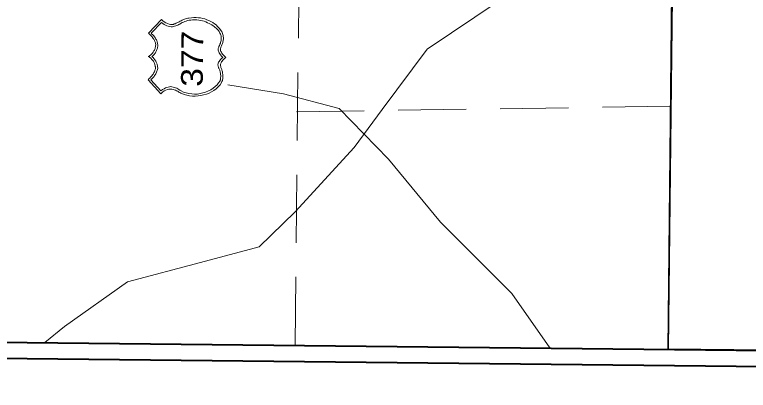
# Model space of a CAD drawing. Extents: x 2356576 to 2377878, y 6966390 to 6990634.
# Drawn here: x 2366013.1 to 2366242.4, y 6968641.2 to 6968758.5 of the extents above; entities that cross this region are included whole.
import ezdxf

# ---------------------------------------------------------------- set-up
doc = ezdxf.new("R2010")
doc.units = 0
doc.header["$LTSCALE"] = 7.1
doc.linetypes.add('MEDIUM_DASHED', pattern=[4.5, 3, -1.5])
doc.layers.add('19', color=7, linetype='Continuous', lineweight=13)
doc.layers.add('8', color=7, linetype='Continuous', lineweight=13)

msp = doc.modelspace()

# ---------------------------------------------------------------- linework, layer by layer
at = {"layer": '19', "lineweight": 35}
for q in [(2366226.339, 6969461.286), (2366922.891, 6968646.236)]:
    msp.add_line((2366217.375, 6968654.072), q, dxfattribs=at)
at = {"layer": '19', "linetype": 'MEDIUM_DASHED'}
for p, q in [((2366100.797, 6968655.28), (2366107.007, 6969254.676)), ((2366218.161, 6968729.912), (2366101.192, 6968728.184))]:
    msp.add_line(p, q, dxfattribs=at)
at = {"layer": '19', "lineweight": 40}
msp.add_lwpolyline([(2363758.773, 6990629.355), (2367158.576, 6990592.767), (2366922.891, 6968646.236), (2363523.088, 6968682.826)], close=True, dxfattribs=at)
at = {"layer": '19', "lineweight": 25}
msp.add_lwpolyline([(2365597.072, 6968660.498), (2366217.375, 6968654.072), (2366223.585, 6969253.468), (2365603.282, 6969259.894)], dxfattribs=at)
at = {"layer": '19'}
for points in [[(2366022.529, 6968656.091), (2366028.702, 6968661.095), (2366048.435, 6968675.023), (2366071.184, 6968681.148), (2366089.535, 6968686.03), (2366100.837, 6968696.954), (2366119.29, 6968717.043), (2366127.961, 6968728.866), (2366142.017, 6968747.71), (2366164.527, 6968762.841)], [(2366058.765, 6968733.811), (2366054.822, 6968738.204), (2366055.064, 6968738.442), (2366055.367, 6968738.707), (2366055.578, 6968738.945), (2366055.792, 6968739.182), (2366056.002, 6968739.42), (2366056.185, 6968739.69), (2366056.368, 6968739.928), (2366056.55, 6968740.167), (2366056.673, 6968740.405), (2366056.795, 6968740.644), (2366056.918, 6968740.911), (2366056.98, 6968741.15), (2366057.043, 6968741.422), (2366057.105, 6968741.629), (2366057.108, 6968741.901), (2366057.111, 6968742.169), (2366057.053, 6968742.35), (2366056.995, 6968742.562), (2366056.97, 6968742.802), (2366056.912, 6968743.043), (2366056.795, 6968743.284), (2366056.705, 6968743.525), (2366056.587, 6968743.734), (2366056.47, 6968743.976), (2366056.292, 6968744.218), (2366056.146, 6968744.431), (2366055.937, 6968744.641), (2366055.791, 6968744.855), (2366055.581, 6968745.037), (2366055.374, 6968745.187), (2366055.135, 6968745.31), (2366054.897, 6968745.432), (2366055.138, 6968745.582), (2366055.38, 6968745.759), (2366055.622, 6968745.905), (2366055.804, 6968746.115), (2366056.014, 6968746.293), (2366056.196, 6968746.531), (2366056.379, 6968746.769), (2366056.533, 6968746.975), (2366056.655, 6968747.214), (2366056.806, 6968747.452), (2366056.901, 6968747.723), (2366056.991, 6968747.962), (2366057.054, 6968748.262), (2366057.116, 6968748.469), (2366057.179, 6968748.769), (2366057.214, 6968749.04), (2366057.216, 6968749.248), (2366057.187, 6968749.489), (2366057.129, 6968749.701), (2366057.072, 6968749.97), (2366056.954, 6968750.183), (2366056.837, 6968750.424), (2366056.719, 6968750.633), (2366056.573, 6968750.879), (2366056.423, 6968751.089), (2366056.246, 6968751.362), (2366056.068, 6968751.572), (2366055.863, 6968751.814), (2366055.653, 6968752.029), (2366055.416, 6968752.299), (2366055.21, 6968752.481), (2366054.972, 6968752.724), (2366059.005, 6968757.034), (2366059.421, 6968756.638), (2366059.869, 6968756.245), (2366060.374, 6968755.968), (2366060.884, 6968755.755), (2366061.39, 6968755.569), (2366061.869, 6968755.472), (2366062.229, 6968755.441), (2366062.529, 6968755.466), (2366062.741, 6968755.495), (2366063.011, 6968755.613), (2366063.251, 6968755.698), (2366063.557, 6968755.815), (2366063.858, 6968755.964), (2366064.16, 6968756.109), (2366064.489, 6968756.257), (2366064.823, 6968756.434), (2366065.185, 6968756.61), (2366065.515, 6968756.787), (2366065.909, 6968756.963), (2366066.238, 6968757.107), (2366066.571, 6968757.224), (2366066.932, 6968757.312), (2366067.262, 6968757.429), (2366067.594, 6968757.453), (2366068.375, 6968757.565), (2366069.096, 6968757.618), (2366069.816, 6968757.61), (2366070.535, 6968757.543), (2366071.222, 6968757.476), (2366071.913, 6968757.32), (2366072.539, 6968757.162), (2366073.197, 6968756.947), (2366073.826, 6968756.701), (2366074.451, 6968756.394)], [(2366075.487, 6968754.823), (2366075.158, 6968755.067), (2366074.772, 6968755.339), (2366074.323, 6968755.583), (2366073.905, 6968755.8), (2366073.399, 6968756.013), (2366072.89, 6968756.23), (2366072.384, 6968756.443), (2366071.813, 6968756.601), (2366071.247, 6968756.727), (2366070.648, 6968756.821), (2366070.017, 6968756.92), (2366069.389, 6968756.927), (2366068.728, 6968756.873), (2366068.155, 6968756.819), (2366067.647, 6968756.765), (2366067.166, 6968756.65), (2366066.712, 6968756.534), (2366066.262, 6968756.359), (2366065.869, 6968756.183), (2366065.479, 6968756.035), (2366065.117, 6968755.831), (2366064.754, 6968755.594), (2366064.453, 6968755.446), (2366064.119, 6968755.269), (2366063.79, 6968755.124), (2366063.456, 6968754.976), (2366063.123, 6968754.891), (2366062.794, 6968754.803), (2366062.434, 6968754.746), (2366062.014, 6968754.751), (2366061.562, 6968754.815), (2366061.115, 6968754.912), (2366060.664, 6968755.037), (2366060.218, 6968755.221), (2366059.801, 6968755.494), (2366059.412, 6968755.77), (2366059.027, 6968756.102), (2366055.78, 6968752.687), (2366056.018, 6968752.473), (2366056.228, 6968752.291), (2366056.434, 6968752.08), (2366056.643, 6968751.866), (2366056.821, 6968751.624), (2366056.998, 6968751.383), (2366057.144, 6968751.141), (2366057.293, 6968750.899), (2366057.411, 6968750.626), (2366057.556, 6968750.385), (2366057.645, 6968750.116), (2366057.703, 6968749.903), (2366057.788, 6968749.634), (2366057.818, 6968749.422), (2366057.844, 6968749.242), (2366057.874, 6968749.033), (2366057.84, 6968748.822), (2366057.837, 6968748.554), (2366057.807, 6968748.314), (2366057.772, 6968748.074), (2366057.681, 6968747.803), (2366057.587, 6968747.596), (2366057.496, 6968747.325), (2366057.374, 6968747.086), (2366057.252, 6968746.88), (2366057.129, 6968746.609), (2366056.975, 6968746.403), (2366056.793, 6968746.192), (2366056.642, 6968745.954), (2366056.429, 6968745.808), (2366056.218, 6968745.598), (2366055.977, 6968745.421), (2366056.215, 6968745.238), (2366056.421, 6968745.088), (2366056.571, 6968744.875), (2366056.749, 6968744.693), (2366056.867, 6968744.512), (2366057.013, 6968744.33), (2366057.163, 6968744.088), (2366057.281, 6968743.939), (2366057.367, 6968743.698), (2366057.485, 6968743.485), (2366057.543, 6968743.277), (2366057.632, 6968743.064), (2366057.658, 6968742.855), (2366057.748, 6968742.642), (2366057.773, 6968742.402), (2366057.803, 6968742.194), (2366057.829, 6968741.953), (2366057.826, 6968741.653), (2366057.763, 6968741.414), (2366057.7, 6968741.115), (2366057.609, 6968740.844), (2366057.486, 6968740.545), (2366057.363, 6968740.278), (2366057.209, 6968740.04), (2366057.058, 6968739.769), (2366056.875, 6968739.471), (2366056.721, 6968739.233), (2366056.51, 6968739.027), (2366056.296, 6968738.757), (2366056.085, 6968738.551)], [(2366074.451, 6968756.394), (2366075.02, 6968756.088), (2366075.556, 6968755.691), (2366076.092, 6968755.297), (2366076.567, 6968754.812), (2366077.042, 6968754.327), (2366077.485, 6968753.81), (2366077.694, 6968753.508), (2366077.839, 6968753.239), (2366077.987, 6968752.905), (2366078.104, 6968752.604), (2366078.221, 6968752.335), (2366078.246, 6968752.035), (2366078.335, 6968751.702), (2366078.36, 6968751.433), (2366078.389, 6968751.133), (2366078.354, 6968750.833), (2366078.323, 6968750.562), (2366078.288, 6968750.29), (2366078.197, 6968749.991), (2366078.163, 6968749.783), (2366078.072, 6968749.512), (2366077.95, 6968749.273), (2366077.856, 6968749.066), (2366077.793, 6968748.827), (2366077.671, 6968748.616), (2366077.581, 6968748.409), (2366077.547, 6968748.198), (2366077.484, 6968747.99), (2366077.422, 6968747.751), (2366077.451, 6968747.51), (2366077.509, 6968747.27), (2366077.594, 6968747.029), (2366077.744, 6968746.755), (2366077.889, 6968746.514), (2366078.126, 6968746.183), (2366078.363, 6968745.881), (2366078.719, 6968745.577), (2366079.107, 6968745.181), (2366078.744, 6968744.857), (2366078.441, 6968744.528), (2366078.138, 6968744.263), (2366077.955, 6968743.993), (2366077.741, 6968743.755), (2366077.618, 6968743.517), (2366077.528, 6968743.309), (2366077.466, 6968743.098), (2366077.432, 6968742.95), (2366077.43, 6968742.71), (2366077.428, 6968742.558), (2366077.518, 6968742.35), (2366077.544, 6968742.169), (2366077.574, 6968741.989), (2366077.692, 6968741.776), (2366077.75, 6968741.567), (2366077.836, 6968741.414), (2366077.894, 6968741.174), (2366077.983, 6968740.933), (2366078.069, 6968740.692), (2366078.098, 6968740.423), (2366078.124, 6968740.183), (2366078.213, 6968739.91), (2366078.238, 6968739.642), (2366078.235, 6968739.342), (2366078.232, 6968739.102), (2366078.229, 6968738.802), (2366078.198, 6968738.47), (2366078.103, 6968738.203), (2366078.04, 6968737.904), (2366077.889, 6968737.605), (2366077.734, 6968737.307), (2366077.307, 6968736.619), (2366076.732, 6968735.965), (2366076.094, 6968735.372), (2366075.4, 6968734.839), (2366074.643, 6968734.367), (2366073.891, 6968733.987), (2366073.048, 6968733.695), (2366072.173, 6968733.432), (2366071.303, 6968733.261), (2366070.43, 6968733.15), (2366069.561, 6968733.071), (2366068.689, 6968733.08), (2366067.79, 6968733.178), (2366066.984, 6968733.338), (2366066.115, 6968733.587), (2366065.37, 6968733.895), (2366065.071, 6968734.018), (2366064.741, 6968734.169), (2366064.442, 6968734.353), (2366064.117, 6968734.568), (2366063.758, 6968734.72), (2366063.4, 6968734.903), (2366063.01, 6968735.087), (2366062.619, 6968735.183), (2366062.2, 6968735.248), (2366061.752, 6968735.252), (2366061.3, 6968735.257), (2366060.85, 6968735.11), (2366060.369, 6968734.967), (2366059.826, 6968734.7)], [(2366055.69, 6968738.195), (2366058.806, 6968734.743), (2366059.29, 6968735.126), (2366059.801, 6968735.393), (2366060.223, 6968735.628), (2366060.645, 6968735.804), (2366061.098, 6968735.919), (2366061.519, 6968735.975), (2366061.88, 6968736.031), (2366062.267, 6968735.967), (2366062.658, 6968735.903), (2366063.017, 6968735.807), (2366063.408, 6968735.683), (2366063.767, 6968735.532), (2366064.093, 6968735.376), (2366064.451, 6968735.165), (2366064.781, 6968734.949), (2366065.138, 6968734.737), (2366065.914, 6968734.337), (2366066.752, 6968734.061), (2366067.557, 6968733.84), (2366068.456, 6968733.743), (2366069.356, 6968733.702), (2366070.228, 6968733.725), (2366071.13, 6968733.863), (2366071.972, 6968734.067), (2366072.815, 6968734.326), (2366073.658, 6968734.677), (2366074.41, 6968735.061), (2366075.135, 6968735.534), (2366075.772, 6968736.035), (2366076.378, 6968736.601), (2366076.865, 6968737.224), (2366077.32, 6968737.879), (2366077.353, 6968738.031), (2366077.443, 6968738.178), (2366077.477, 6968738.39), (2366077.479, 6968738.63), (2366077.51, 6968738.837), (2366077.544, 6968739.049), (2366077.546, 6968739.289), (2366077.517, 6968739.557), (2366077.492, 6968739.798), (2366077.494, 6968740.038), (2366077.437, 6968740.278), (2366077.407, 6968740.519), (2366077.349, 6968740.759), (2366077.292, 6968740.972), (2366077.206, 6968741.181), (2366077.176, 6968741.361), (2366077.058, 6968741.574), (2366076.972, 6968741.755), (2366076.882, 6968741.936), (2366076.796, 6968742.117), (2366076.738, 6968742.358), (2366076.708, 6968742.506), (2366076.65, 6968742.719), (2366076.652, 6968742.959), (2366076.714, 6968743.166), (2366076.777, 6968743.437), (2366076.872, 6968743.676), (2366077.022, 6968743.883), (2366077.205, 6968744.181), (2366077.508, 6968744.478), (2366077.812, 6968744.835), (2366078.175, 6968745.163), (2366077.792, 6968745.587), (2366077.463, 6968745.95), (2366077.226, 6968746.253), (2366077.022, 6968746.583), (2366076.905, 6968746.884), (2366076.815, 6968747.125), (2366076.758, 6968747.398), (2366076.761, 6968747.666), (2366076.763, 6968747.906), (2366076.826, 6968748.117), (2366076.92, 6968748.356), (2366076.983, 6968748.595), (2366077.105, 6968748.834), (2366077.228, 6968749.073), (2366077.29, 6968749.312), (2366077.441, 6968749.579), (2366077.504, 6968749.85), (2366077.599, 6968750.149), (2366077.63, 6968750.417), (2366077.664, 6968750.688), (2366077.667, 6968750.988), (2366077.671, 6968751.288), (2366077.641, 6968751.561), (2366077.617, 6968751.861), (2366077.528, 6968752.162), (2366077.47, 6968752.431), (2366077.293, 6968752.704), (2366077.176, 6968753.006), (2366076.999, 6968753.247), (2366076.822, 6968753.549), (2366076.585, 6968753.82), (2366076.32, 6968754.095), (2366076.11, 6968754.337), (2366075.784, 6968754.548), (2366075.487, 6968754.823)], [(2366056.085, 6968738.551), (2366055.872, 6968738.374), (2366055.69, 6968738.195)], [(2366079.707, 6968736.627), (2366097.111, 6968733.806), (2366114.556, 6968729.185), (2366129.993, 6968713.392), (2366146.198, 6968693.691), (2366168.5, 6968671.411), (2366180.357, 6968654.455)], [(2366059.826, 6968734.7), (2366059.31, 6968734.318), (2366058.765, 6968733.811)]]:
    msp.add_lwpolyline(points, dxfattribs=at)
at = {"layer": '8', "lineweight": 35}
for q in [(2366226.339, 6969461.286), (2366922.891, 6968646.236)]:
    msp.add_line((2366217.375, 6968654.072), q, dxfattribs=at)
at = {"layer": '8', "linetype": 'MEDIUM_DASHED'}
for p, q in [((2366100.797, 6968655.28), (2366107.007, 6969254.676)), ((2366218.161, 6968729.912), (2366101.192, 6968728.184))]:
    msp.add_line(p, q, dxfattribs=at)
at = {"layer": '8', "lineweight": 40}
for points in [[(2363753.827, 6990634.409), (2367163.63, 6990597.713), (2366927.837, 6968641.182), (2363518.034, 6968677.88)], [(2363758.773, 6990629.355), (2367158.576, 6990592.767), (2366922.891, 6968646.236), (2363523.088, 6968682.826)]]:
    msp.add_lwpolyline(points, close=True, dxfattribs=at)
at = {"layer": '8', "lineweight": 25}
msp.add_lwpolyline([(2365597.072, 6968660.498), (2366217.375, 6968654.072), (2366223.585, 6969253.468), (2365603.282, 6969259.894)], dxfattribs=at)
at = {"layer": '8'}
for points in [[(2366022.529, 6968656.091), (2366028.702, 6968661.095), (2366048.435, 6968675.023), (2366071.184, 6968681.148), (2366089.535, 6968686.03), (2366100.837, 6968696.954), (2366119.29, 6968717.043), (2366127.961, 6968728.866), (2366142.017, 6968747.71), (2366164.527, 6968762.841)], [(2366058.765, 6968733.811), (2366054.822, 6968738.204), (2366055.064, 6968738.442), (2366055.367, 6968738.707), (2366055.578, 6968738.945), (2366055.792, 6968739.182), (2366056.002, 6968739.42), (2366056.185, 6968739.69), (2366056.368, 6968739.928), (2366056.55, 6968740.167), (2366056.673, 6968740.405), (2366056.795, 6968740.644), (2366056.918, 6968740.911), (2366056.98, 6968741.15), (2366057.043, 6968741.422), (2366057.105, 6968741.629), (2366057.108, 6968741.901), (2366057.111, 6968742.169), (2366057.053, 6968742.35), (2366056.995, 6968742.562), (2366056.97, 6968742.802), (2366056.912, 6968743.043), (2366056.795, 6968743.284), (2366056.705, 6968743.525), (2366056.587, 6968743.734), (2366056.47, 6968743.976), (2366056.292, 6968744.218), (2366056.146, 6968744.431), (2366055.937, 6968744.641), (2366055.791, 6968744.855), (2366055.581, 6968745.037), (2366055.374, 6968745.187), (2366055.135, 6968745.31), (2366054.897, 6968745.432), (2366055.138, 6968745.582), (2366055.38, 6968745.759), (2366055.622, 6968745.905), (2366055.804, 6968746.115), (2366056.014, 6968746.293), (2366056.196, 6968746.531), (2366056.379, 6968746.769), (2366056.533, 6968746.975), (2366056.655, 6968747.214), (2366056.806, 6968747.452), (2366056.901, 6968747.723), (2366056.991, 6968747.962), (2366057.054, 6968748.262), (2366057.116, 6968748.469), (2366057.179, 6968748.769), (2366057.214, 6968749.04), (2366057.216, 6968749.248), (2366057.187, 6968749.489), (2366057.129, 6968749.701), (2366057.072, 6968749.97), (2366056.954, 6968750.183), (2366056.837, 6968750.424), (2366056.719, 6968750.633), (2366056.573, 6968750.879), (2366056.423, 6968751.089), (2366056.246, 6968751.362), (2366056.068, 6968751.572), (2366055.863, 6968751.814), (2366055.653, 6968752.029), (2366055.416, 6968752.299), (2366055.21, 6968752.481), (2366054.972, 6968752.724), (2366059.005, 6968757.034), (2366059.421, 6968756.638), (2366059.869, 6968756.245), (2366060.374, 6968755.968), (2366060.884, 6968755.755), (2366061.39, 6968755.569), (2366061.869, 6968755.472), (2366062.229, 6968755.441), (2366062.529, 6968755.466), (2366062.741, 6968755.495), (2366063.011, 6968755.613), (2366063.251, 6968755.698), (2366063.557, 6968755.815), (2366063.858, 6968755.964), (2366064.16, 6968756.109), (2366064.489, 6968756.257), (2366064.823, 6968756.434), (2366065.185, 6968756.61), (2366065.515, 6968756.787), (2366065.909, 6968756.963), (2366066.238, 6968757.107), (2366066.571, 6968757.224), (2366066.932, 6968757.312), (2366067.262, 6968757.429), (2366067.594, 6968757.453), (2366068.375, 6968757.565), (2366069.096, 6968757.618), (2366069.816, 6968757.61), (2366070.535, 6968757.543), (2366071.222, 6968757.476), (2366071.913, 6968757.32), (2366072.539, 6968757.162), (2366073.197, 6968756.947), (2366073.826, 6968756.701), (2366074.451, 6968756.394)], [(2366075.487, 6968754.823), (2366075.158, 6968755.067), (2366074.772, 6968755.339), (2366074.323, 6968755.583), (2366073.905, 6968755.8), (2366073.399, 6968756.013), (2366072.89, 6968756.23), (2366072.384, 6968756.443), (2366071.813, 6968756.601), (2366071.247, 6968756.727), (2366070.648, 6968756.821), (2366070.017, 6968756.92), (2366069.389, 6968756.927), (2366068.728, 6968756.873), (2366068.155, 6968756.819), (2366067.647, 6968756.765), (2366067.166, 6968756.65), (2366066.712, 6968756.534), (2366066.262, 6968756.359), (2366065.869, 6968756.183), (2366065.479, 6968756.035), (2366065.117, 6968755.831), (2366064.754, 6968755.594), (2366064.453, 6968755.446), (2366064.119, 6968755.269), (2366063.79, 6968755.124), (2366063.456, 6968754.976), (2366063.123, 6968754.891), (2366062.794, 6968754.803), (2366062.434, 6968754.746), (2366062.014, 6968754.751), (2366061.562, 6968754.815), (2366061.115, 6968754.912), (2366060.664, 6968755.037), (2366060.218, 6968755.221), (2366059.801, 6968755.494), (2366059.412, 6968755.77), (2366059.027, 6968756.102), (2366055.78, 6968752.687), (2366056.018, 6968752.473), (2366056.228, 6968752.291), (2366056.434, 6968752.08), (2366056.643, 6968751.866), (2366056.821, 6968751.624), (2366056.998, 6968751.383), (2366057.144, 6968751.141), (2366057.293, 6968750.899), (2366057.411, 6968750.626), (2366057.556, 6968750.385), (2366057.645, 6968750.116), (2366057.703, 6968749.903), (2366057.788, 6968749.634), (2366057.818, 6968749.422), (2366057.844, 6968749.242), (2366057.874, 6968749.033), (2366057.84, 6968748.822), (2366057.837, 6968748.554), (2366057.807, 6968748.314), (2366057.772, 6968748.074), (2366057.681, 6968747.803), (2366057.587, 6968747.596), (2366057.496, 6968747.325), (2366057.374, 6968747.086), (2366057.252, 6968746.88), (2366057.129, 6968746.609), (2366056.975, 6968746.403), (2366056.793, 6968746.192), (2366056.642, 6968745.954), (2366056.429, 6968745.808), (2366056.218, 6968745.598), (2366055.977, 6968745.421), (2366056.215, 6968745.238), (2366056.421, 6968745.088), (2366056.571, 6968744.875), (2366056.749, 6968744.693), (2366056.867, 6968744.512), (2366057.013, 6968744.33), (2366057.163, 6968744.088), (2366057.281, 6968743.939), (2366057.367, 6968743.698), (2366057.485, 6968743.485), (2366057.543, 6968743.277), (2366057.632, 6968743.064), (2366057.658, 6968742.855), (2366057.748, 6968742.642), (2366057.773, 6968742.402), (2366057.803, 6968742.194), (2366057.829, 6968741.953), (2366057.826, 6968741.653), (2366057.763, 6968741.414), (2366057.7, 6968741.115), (2366057.609, 6968740.844), (2366057.486, 6968740.545), (2366057.363, 6968740.278), (2366057.209, 6968740.04), (2366057.058, 6968739.769), (2366056.875, 6968739.471), (2366056.721, 6968739.233), (2366056.51, 6968739.027), (2366056.296, 6968738.757), (2366056.085, 6968738.551)], [(2366074.451, 6968756.394), (2366075.02, 6968756.088), (2366075.556, 6968755.691), (2366076.092, 6968755.297), (2366076.567, 6968754.812), (2366077.042, 6968754.327), (2366077.485, 6968753.81), (2366077.694, 6968753.508), (2366077.839, 6968753.239), (2366077.987, 6968752.905), (2366078.104, 6968752.604), (2366078.221, 6968752.335), (2366078.246, 6968752.035), (2366078.335, 6968751.702), (2366078.36, 6968751.433), (2366078.389, 6968751.133), (2366078.354, 6968750.833), (2366078.323, 6968750.562), (2366078.288, 6968750.29), (2366078.197, 6968749.991), (2366078.163, 6968749.783), (2366078.072, 6968749.512), (2366077.95, 6968749.273), (2366077.856, 6968749.066), (2366077.793, 6968748.827), (2366077.671, 6968748.616), (2366077.581, 6968748.409), (2366077.547, 6968748.198), (2366077.484, 6968747.99), (2366077.422, 6968747.751), (2366077.451, 6968747.51), (2366077.509, 6968747.27), (2366077.594, 6968747.029), (2366077.744, 6968746.755), (2366077.889, 6968746.514), (2366078.126, 6968746.183), (2366078.363, 6968745.881), (2366078.719, 6968745.577), (2366079.107, 6968745.181), (2366078.744, 6968744.857), (2366078.441, 6968744.528), (2366078.138, 6968744.263), (2366077.955, 6968743.993), (2366077.741, 6968743.755), (2366077.618, 6968743.517), (2366077.528, 6968743.309), (2366077.466, 6968743.098), (2366077.432, 6968742.95), (2366077.43, 6968742.71), (2366077.428, 6968742.558), (2366077.518, 6968742.35), (2366077.544, 6968742.169), (2366077.574, 6968741.989), (2366077.692, 6968741.776), (2366077.75, 6968741.567), (2366077.836, 6968741.414), (2366077.894, 6968741.174), (2366077.983, 6968740.933), (2366078.069, 6968740.692), (2366078.098, 6968740.423), (2366078.124, 6968740.183), (2366078.213, 6968739.91), (2366078.238, 6968739.642), (2366078.235, 6968739.342), (2366078.232, 6968739.102), (2366078.229, 6968738.802), (2366078.198, 6968738.47), (2366078.103, 6968738.203), (2366078.04, 6968737.904), (2366077.889, 6968737.605), (2366077.734, 6968737.307), (2366077.307, 6968736.619), (2366076.732, 6968735.965), (2366076.094, 6968735.372), (2366075.4, 6968734.839), (2366074.643, 6968734.367), (2366073.891, 6968733.987), (2366073.048, 6968733.695), (2366072.173, 6968733.432), (2366071.303, 6968733.261), (2366070.43, 6968733.15), (2366069.561, 6968733.071), (2366068.689, 6968733.08), (2366067.79, 6968733.178), (2366066.984, 6968733.338), (2366066.115, 6968733.587), (2366065.37, 6968733.895), (2366065.071, 6968734.018), (2366064.741, 6968734.169), (2366064.442, 6968734.353), (2366064.117, 6968734.568), (2366063.758, 6968734.72), (2366063.4, 6968734.903), (2366063.01, 6968735.087), (2366062.619, 6968735.183), (2366062.2, 6968735.248), (2366061.752, 6968735.252), (2366061.3, 6968735.257), (2366060.85, 6968735.11), (2366060.369, 6968734.967), (2366059.826, 6968734.7)], [(2366055.69, 6968738.195), (2366058.806, 6968734.743), (2366059.29, 6968735.126), (2366059.801, 6968735.393), (2366060.223, 6968735.628), (2366060.645, 6968735.804), (2366061.098, 6968735.919), (2366061.519, 6968735.975), (2366061.88, 6968736.031), (2366062.267, 6968735.967), (2366062.658, 6968735.903), (2366063.017, 6968735.807), (2366063.408, 6968735.683), (2366063.767, 6968735.532), (2366064.093, 6968735.376), (2366064.451, 6968735.165), (2366064.781, 6968734.949), (2366065.138, 6968734.737), (2366065.914, 6968734.337), (2366066.752, 6968734.061), (2366067.557, 6968733.84), (2366068.456, 6968733.743), (2366069.356, 6968733.702), (2366070.228, 6968733.725), (2366071.13, 6968733.863), (2366071.972, 6968734.067), (2366072.815, 6968734.326), (2366073.658, 6968734.677), (2366074.41, 6968735.061), (2366075.135, 6968735.534), (2366075.772, 6968736.035), (2366076.378, 6968736.601), (2366076.865, 6968737.224), (2366077.32, 6968737.879), (2366077.353, 6968738.031), (2366077.443, 6968738.178), (2366077.477, 6968738.39), (2366077.479, 6968738.63), (2366077.51, 6968738.837), (2366077.544, 6968739.049), (2366077.546, 6968739.289), (2366077.517, 6968739.557), (2366077.492, 6968739.798), (2366077.494, 6968740.038), (2366077.437, 6968740.278), (2366077.407, 6968740.519), (2366077.349, 6968740.759), (2366077.292, 6968740.972), (2366077.206, 6968741.181), (2366077.176, 6968741.361), (2366077.058, 6968741.574), (2366076.972, 6968741.755), (2366076.882, 6968741.936), (2366076.796, 6968742.117), (2366076.738, 6968742.358), (2366076.708, 6968742.506), (2366076.65, 6968742.719), (2366076.652, 6968742.959), (2366076.714, 6968743.166), (2366076.777, 6968743.437), (2366076.872, 6968743.676), (2366077.022, 6968743.883), (2366077.205, 6968744.181), (2366077.508, 6968744.478), (2366077.812, 6968744.835), (2366078.175, 6968745.163), (2366077.792, 6968745.587), (2366077.463, 6968745.95), (2366077.226, 6968746.253), (2366077.022, 6968746.583), (2366076.905, 6968746.884), (2366076.815, 6968747.125), (2366076.758, 6968747.398), (2366076.761, 6968747.666), (2366076.763, 6968747.906), (2366076.826, 6968748.117), (2366076.92, 6968748.356), (2366076.983, 6968748.595), (2366077.105, 6968748.834), (2366077.228, 6968749.073), (2366077.29, 6968749.312), (2366077.441, 6968749.579), (2366077.504, 6968749.85), (2366077.599, 6968750.149), (2366077.63, 6968750.417), (2366077.664, 6968750.688), (2366077.667, 6968750.988), (2366077.671, 6968751.288), (2366077.641, 6968751.561), (2366077.617, 6968751.861), (2366077.528, 6968752.162), (2366077.47, 6968752.431), (2366077.293, 6968752.704), (2366077.176, 6968753.006), (2366076.999, 6968753.247), (2366076.822, 6968753.549), (2366076.585, 6968753.82), (2366076.32, 6968754.095), (2366076.11, 6968754.337), (2366075.784, 6968754.548), (2366075.487, 6968754.823)], [(2366056.085, 6968738.551), (2366055.872, 6968738.374), (2366055.69, 6968738.195)], [(2366079.707, 6968736.627), (2366097.111, 6968733.806), (2366114.556, 6968729.185), (2366129.993, 6968713.392), (2366146.198, 6968693.691), (2366168.5, 6968671.411), (2366180.357, 6968654.455)], [(2366059.826, 6968734.7), (2366059.31, 6968734.318), (2366058.765, 6968733.811)]]:
    msp.add_lwpolyline(points, dxfattribs=at)

# ---------------------------------------------------------------- texts
at = {"layer": '19', "width": 1.15}
msp.add_text('377', height=6.798, rotation=89.406, dxfattribs=at).set_placement((2366071.9, 6968735.987))
at = {"layer": '8', "width": 1.15}
msp.add_text('377', height=6.798, rotation=89.406, dxfattribs=at).set_placement((2366071.9, 6968735.987))

doc.saveas('drawing.dxf')
